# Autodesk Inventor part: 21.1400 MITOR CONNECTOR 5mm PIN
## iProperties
Created: 2007-05
Part Number: 21.1400 MITOR CONNECTOR 5mm PIN
Material: Alloy Steel
Document SubType Name: Modeling
Designer: Andy Moles
Density: 7.85 g/cm^3
Author: Andy Moles
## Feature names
1. Revolution1
